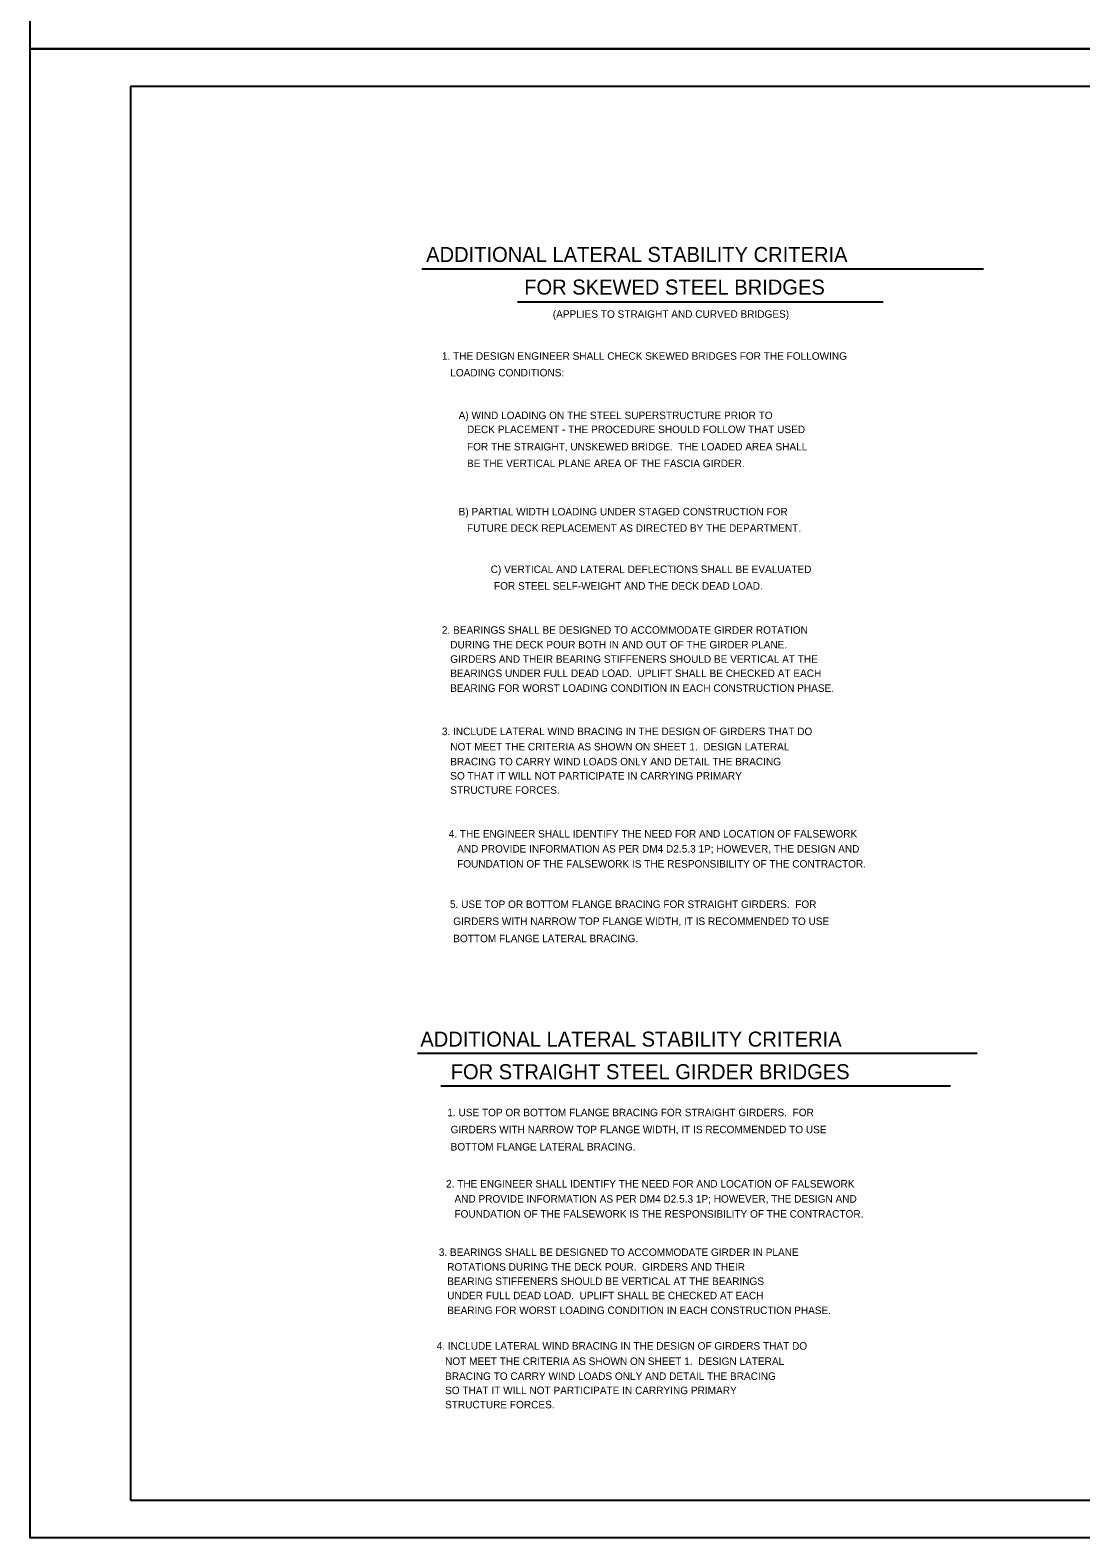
# Model space of a CAD drawing. Extents: x 30 to 2621, y -33 to 1155.
# Drawn here: x 30 to 450, y -33 to 568 of the extents above; entities that cross this region are included whole.
import ezdxf

# ---------------------------------------------------------------- set-up
doc = ezdxf.new("R2010")
doc.units = 0
doc.layers.add('1', color=7, linetype='Continuous')
doc.layers.add('PLT-BNDY', color=7, linetype='Continuous')

msp = doc.modelspace()

# ---------------------------------------------------------------- linework, layer by layer
at = {"layer": '1'}
for p, q in [((70.5, 546), (70.5, -18)), ((856.5, 546), (70.5, 546)), ((410.81, 473.19), (186.8, 473.19)), ((370.74, 459.93), (224.92, 459.93)), ((408.37, 160.17), (184.99, 160.17)), ((397.73, 147.25), (194.3, 147.25)), ((70.5, -18), (856.5, -18))]:
    msp.add_line(p, q, dxfattribs=at)
at = {"layer": 'PLT-BNDY'}
for points in [[(30.5, 1155), (871.5, 1155), (871.5, 561), (30.5, 561)], [(30.5, 561), (871.5, 561), (871.5, -33), (30.5, -33)]]:
    msp.add_lwpolyline(points, close=True, dxfattribs=at)

# ---------------------------------------------------------------- texts
at = {"layer": '1'}
for s, height, p in [('ADDITIONAL LATERAL STABILITY CRITERIA', 6, (188.48, 476.01)), ('FOR SKEWED STEEL BRIDGES', 6, (227.6, 463.01)), ('(APPLIES TO STRAIGHT AND CURVED BRIDGES)', 3, (239, 453.74)), (' 1. THE DESIGN ENGINEER SHALL CHECK SKEWED BRIDGES FOR THE FOLLOWING', 3, (193.64, 437)), ('    LOADING CONDITIONS:', 3, (193.64, 430.35)), ('       A) WIND LOADING ON THE STEEL SUPERSTRUCTURE PRIOR TO', 3, (193.64, 413.32)), ('          DECK PLACEMENT - THE PROCEDURE SHOULD FOLLOW THAT USED', 3, (193.64, 407.73)), ('          FOR THE STRAIGHT, UNSKEWED BRIDGE.  THE LOADED AREA SHALL', 3, (193.64, 400.83)), ('          BE THE VERTICAL PLANE AREA OF THE FASCIA GIRDER. ', 3, (193.64, 394.17)), ('       B) PARTIAL WIDTH LOADING UNDER STAGED CONSTRUCTION FOR', 3, (193.64, 374.9)), ('          FUTURE DECK REPLACEMENT AS DIRECTED BY THE DEPARTMENT.', 3, (193.64, 368.37)), ('C) VERTICAL AND LATERAL DEFLECTIONS SHALL BE EVALUATED', 3, (214.23, 351.92)), ('    FOR STEEL SELF-WEIGHT AND THE DECK DEAD LOAD.', 3, (211.09, 345.28)), (' 2. BEARINGS SHALL BE DESIGNED TO ACCOMMODATE GIRDER ROTATION', 3, (193.64, 327.69)), ('    DURING THE DECK POUR BOTH IN AND OUT OF THE GIRDER PLANE.', 3, (193.64, 321.83)), ('    GIRDERS AND THEIR BEARING STIFFENERS SHOULD BE VERTICAL AT THE', 3, (193.64, 316.1)), ('    BEARINGS UNDER FULL DEAD LOAD.  UPLIFT SHALL BE CHECKED AT EACH', 3, (193.64, 310.42)), ('    BEARING FOR WORST LOADING CONDITION IN EACH CONSTRUCTION PHASE.', 3, (193.64, 304.51)), (' 3. INCLUDE LATERAL WIND BRACING IN THE DESIGN OF GIRDERS THAT DO', 3, (193.64, 287.24)), ('    NOT MEET THE CRITERIA AS SHOWN ON SHEET 1.  DESIGN LATERAL', 3, (193.64, 281.14)), ('    BRACING TO CARRY WIND LOADS ONLY AND DETAIL THE BRACING', 3, (193.64, 275.18)), ('    SO THAT IT WILL NOT PARTICIPATE IN CARRYING PRIMARY', 3, (193.64, 269.51)), ('    STRUCTURE FORCES.', 3, (193.64, 263.83)), ('4. THE ENGINEER SHALL IDENTIFY THE NEED FOR AND LOCATION OF FALSEWORK', 3, (197.48, 246.39)), ('   AND PROVIDE INFORMATION AS PER DM4 D2.5.3 1P; HOWEVER, THE DESIGN AND', 3, (197.48, 240.39)), ('   FOUNDATION OF THE FALSEWORK IS THE RESPONSIBILITY OF THE CONTRACTOR.', 3, (197.48, 234.39)), ('5. USE TOP OR BOTTOM FLANGE BRACING FOR STRAIGHT GIRDERS.  FOR', 3, (197.97, 218.3)), ('    GIRDERS WITH NARROW TOP FLANGE WIDTH, IT IS RECOMMENDED TO USE', 3, (194.83, 211.49)), ('    BOTTOM FLANGE LATERAL BRACING.', 3, (194.83, 204.62)), ('ADDITIONAL LATERAL STABILITY CRITERIA', 6, (186.15, 162.97)), ('FOR STRAIGHT STEEL GIRDER BRIDGES', 6, (198.27, 149.97)), ('1. USE TOP OR BOTTOM FLANGE BRACING FOR STRAIGHT GIRDERS.  FOR', 3, (196.92, 135.2)), ('    GIRDERS WITH NARROW TOP FLANGE WIDTH, IT IS RECOMMENDED TO USE', 3, (193.78, 128.4)), ('    BOTTOM FLANGE LATERAL BRACING.', 3, (193.78, 121.53)), ('2. THE ENGINEER SHALL IDENTIFY THE NEED FOR AND LOCATION OF FALSEWORK', 3, (196.43, 106.74)), ('   AND PROVIDE INFORMATION AS PER DM4 D2.5.3 1P; HOWEVER, THE DESIGN AND', 3, (196.43, 100.74)), ('   FOUNDATION OF THE FALSEWORK IS THE RESPONSIBILITY OF THE CONTRACTOR.', 3, (196.43, 94.74)), (' 3. BEARINGS SHALL BE DESIGNED TO ACCOMMODATE GIRDER IN PLANE', 3, (192.42, 79.46)), ('    ROTATIONS DURING THE DECK POUR.  GIRDERS AND THEIR', 3, (192.42, 73.6)), ('    BEARING STIFFENERS SHOULD BE VERTICAL AT THE BEARINGS', 3, (192.42, 67.87)), ('    UNDER FULL DEAD LOAD.  UPLIFT SHALL BE CHECKED AT EACH', 3, (192.42, 62.19)), ('    BEARING FOR WORST LOADING CONDITION IN EACH CONSTRUCTION PHASE.', 3, (192.42, 56.28)), (' 4. INCLUDE LATERAL WIND BRACING IN THE DESIGN OF GIRDERS THAT DO', 3, (191.57, 42.07)), ('    NOT MEET THE CRITERIA AS SHOWN ON SHEET 1.  DESIGN LATERAL', 3, (191.57, 35.96)), ('    BRACING TO CARRY WIND LOADS ONLY AND DETAIL THE BRACING', 3, (191.57, 30.01)), ('    SO THAT IT WILL NOT PARTICIPATE IN CARRYING PRIMARY', 3, (191.57, 24.33)), ('    STRUCTURE FORCES.', 3, (191.57, 18.66))]:
    msp.add_text(s, height=height, dxfattribs=at).set_placement(p)

doc.saveas('drawing.dxf')
